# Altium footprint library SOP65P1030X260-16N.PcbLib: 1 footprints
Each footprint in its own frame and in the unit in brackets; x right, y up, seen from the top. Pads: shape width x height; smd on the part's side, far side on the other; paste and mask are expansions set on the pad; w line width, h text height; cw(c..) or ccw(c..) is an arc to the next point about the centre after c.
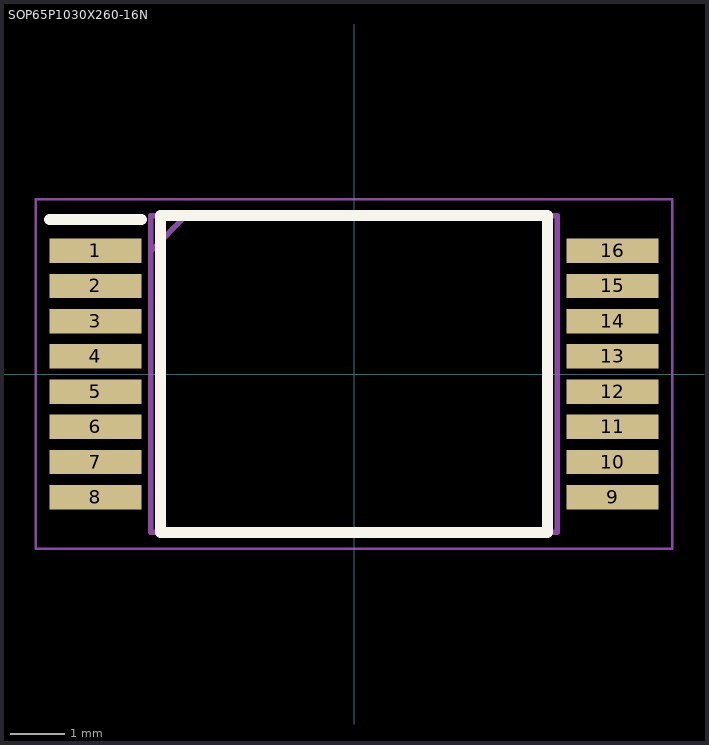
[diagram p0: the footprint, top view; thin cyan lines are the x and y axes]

## SOP65P1030X260-16N [mm]
pads (16):
  rect 1.7x0.45 smd: 1(-4.775,2.275) 2(-4.775,1.625) 3(-4.775,0.975) 4(-4.775,0.325) 5(-4.775,-0.325) 6(-4.775,-0.975) 7(-4.775,-1.625) 8(-4.775,-2.275) 9(4.775,-2.275) 10(4.775,-1.625) 11(4.775,-0.975) 12(4.775,-0.325) 13(4.775,0.325) 14(4.775,0.975) 15(4.775,1.625) 16(4.775,2.275)
Top Overlay:
  lines w0.2: -5.625,2.85 -3.925,2.85 ; -3.575,-2.925 3.575,-2.925 3.575,2.925 -3.575,2.925 -3.575,-2.925
Mechanical 15:
  lines w0.1: -3.75,2.275 -3.1,2.925 ; -3.75,-2.925 3.75,-2.925 3.75,2.925 -3.75,2.925 -3.75,-2.925
Mechanical 20:
  lines w0.05: -5.875,-3.225 5.875,-3.225 5.875,3.225 -5.875,3.225 -5.875,-3.225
